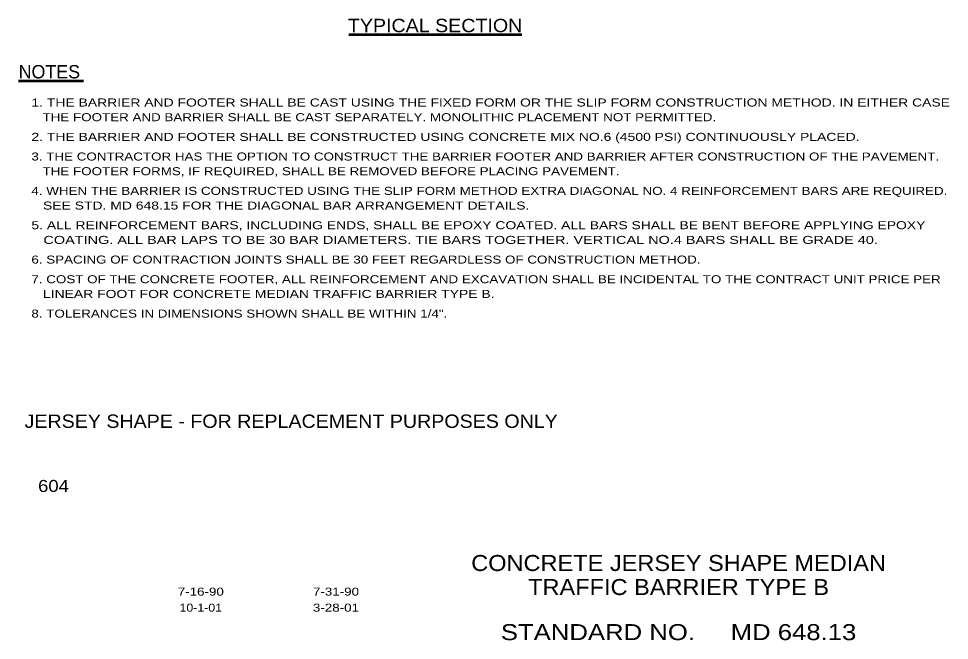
# Model space of a CAD drawing. Extents: x -9.07 to -2.08, y 8.04 to 17.77.
# Drawn here: x -9.07 to -2.09, y 8.04 to 12.69 of the extents above; entities that cross this region are included whole.
import ezdxf
from ezdxf.enums import TextEntityAlignment as Align

# ---------------------------------------------------------------- set-up
doc = ezdxf.new("R2010")
doc.units = 0
doc.header["$LTSCALE"] = 0.024
doc.layers.add('12', color=7, linetype='Continuous', lineweight=53)
doc.layers.add('13', color=7, linetype='Continuous', lineweight=53)

msp = doc.modelspace()

# ---------------------------------------------------------------- linework, layer by layer
at = {"layer": '12'}
msp.add_line((-6.59417, 12.57383), (-5.29733, 12.57383), dxfattribs=at)
at = {"layer": '13'}
msp.add_line((-9.07033, 12.22917), (-8.58417, 12.22917), dxfattribs=at)

# ---------------------------------------------------------------- texts
at = {"layer": '12', "width": 1.1}
msp.add_text('TYPICAL SECTION', height=0.1, dxfattribs=at).set_placement((-5.94833, 12.5925), align=Align.CENTER)
msp.add_text('JERSEY SHAPE - FOR REPLACEMENT PURPOSES ONLY', height=0.1, dxfattribs=at).set_placement((-9.02567, 9.62792))
at = {"layer": '13'}
msp.add_text('NOTES', height=0.1, dxfattribs=at).set_placement((-9.07033, 12.24625))
for s, width, p in [('1. THE BARRIER AND FOOTER SHALL BE CAST USING THE FIXED FORM OR THE SLIP FORM CONSTRUCTION METHOD. IN EITHER CASE', 1.3, (-8.97458, 12.03558)), ('   THE FOOTER AND BARRIER SHALL BE CAST SEPARATELY. MONOLITHIC PLACEMENT NOT PERMITTED.', 1.25, (-8.97458, 11.92558)), ('2. THE BARRIER AND FOOTER SHALL BE CONSTRUCTED USING CONCRETE MIX NO.6 (4500 PSI) CONTINUOUSLY PLACED.', 1.3, (-8.97458, 11.77817)), ('3. THE CONTRACTOR HAS THE OPTION TO CONSTRUCT THE BARRIER FOOTER AND BARRIER AFTER CONSTRUCTION OF THE PAVEMENT.', 1.25, (-8.97458, 11.63083)), ('   THE FOOTER FORMS, IF REQUIRED, SHALL BE REMOVED BEFORE PLACING PAVEMENT.', 1.25, (-8.97458, 11.52083)), ('4. WHEN THE BARRIER IS CONSTRUCTED USING THE SLIP FORM METHOD EXTRA DIAGONAL NO. 4 REINFORCEMENT BARS ARE REQUIRED.', 1.25, (-8.97458, 11.3735)), ('   SEE STD. MD 648.15 FOR THE DIAGONAL BAR ARRANGEMENT DETAILS.', 1.3, (-8.97458, 11.2635)), ('5. ALL REINFORCEMENT BARS, INCLUDING ENDS, SHALL BE EPOXY COATED. ALL BARS SHALL BE BENT BEFORE APPLYING EPOXY', 1.3, (-8.97458, 11.11617)), ('   COATING. ALL BAR LAPS TO BE 30 BAR DIAMETERS. TIE BARS TOGETHER. VERTICAL NO.4 BARS SHALL BE GRADE 40.', 1.35, (-8.97458, 11.00608)), ('6. SPACING OF CONTRACTION JOINTS SHALL BE 30 FEET REGARDLESS OF CONSTRUCTION METHOD.', 1.25, (-8.97458, 10.85875)), ('7. COST OF THE CONCRETE FOOTER, ALL REINFORCEMENT AND EXCAVATION SHALL BE INCIDENTAL TO THE CONTRACT UNIT PRICE PER', 1.25, (-8.97458, 10.71142)), ('   LINEAR FOOT FOR CONCRETE MEDIAN TRAFFIC BARRIER TYPE B.', 1.3, (-8.97458, 10.60142)), ('8. TOLERANCES IN DIMENSIONS SHOWN SHALL BE WITHIN 1/4".', 1.25, (-8.97458, 10.45408))]:
    msp.add_text(s, height=0.06001, dxfattribs=dict(at, width=width)).set_placement(p)
for s, height, width, p in [('604', 0.09001, 1.15, (-8.80896, 9.14775)), ('CONCRETE JERSEY SHAPE MEDIAN', 0.12, 1.1, (-4.12296, 8.5555)), ('TRAFFIC BARRIER TYPE B', 0.12, 1.1, (-4.12296, 8.3755)), ('7-16-90', 0.06, 1.25, (-7.70467, 8.371)), ('7-31-90', 0.06, 1.25, (-6.69142, 8.371)), ('10-1-01', 0.06, 1.15, (-7.70467, 8.251)), ('3-28-01', 0.06, 1.25, (-6.69146, 8.251)), ('STANDARD NO.     MD 648.13', 0.12, 1.2, (-4.12296, 8.0375))]:
    msp.add_text(s, height=height, dxfattribs=dict(at, width=width)).set_placement(p, align=Align.CENTER)

doc.saveas('drawing.dxf')
